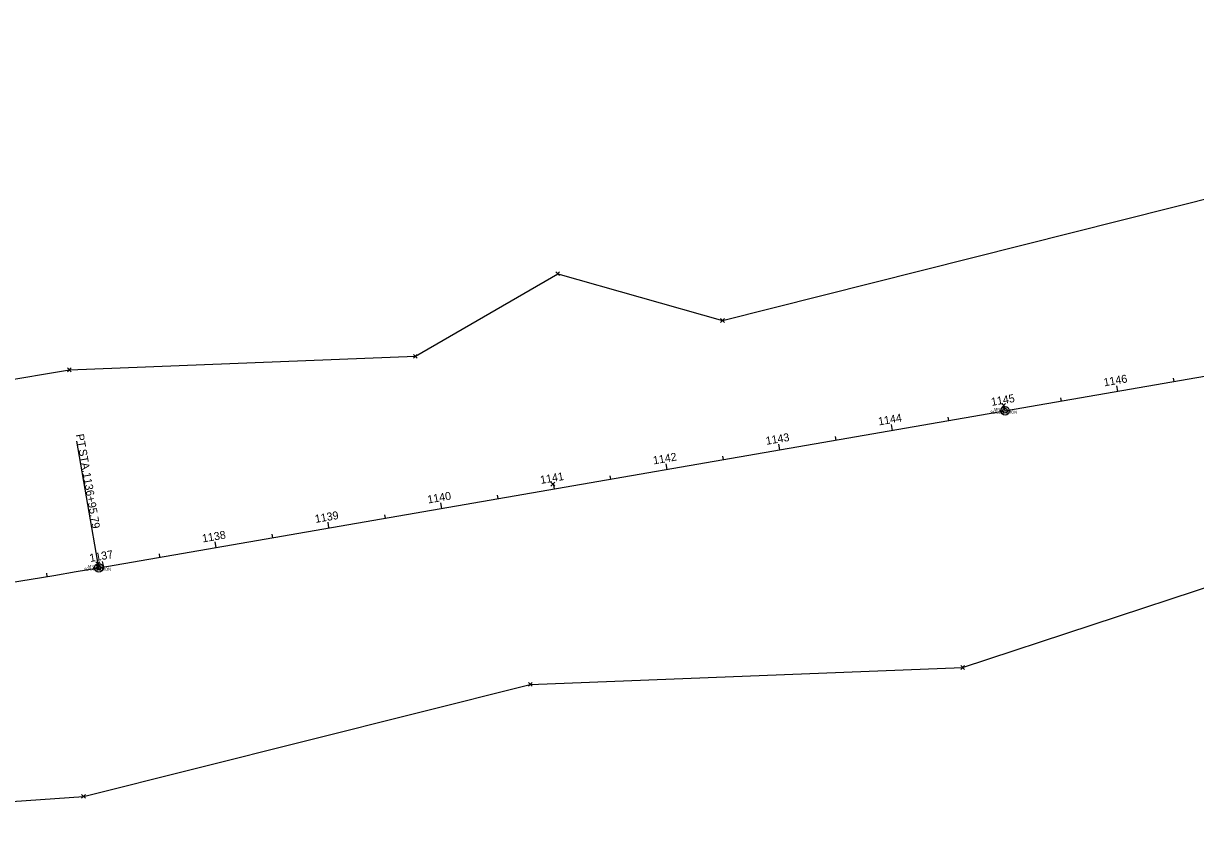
# Model space of a CAD drawing. Extents: x 2082101 to 2090447, y 708207 to 709766.
# Drawn here: x 2085236 to 2086260, y 708322 to 709029 of the extents above; entities that cross this region are included whole.
import ezdxf

# ---------------------------------------------------------------- set-up
doc = ezdxf.new("R2010")
doc.units = 0
for name, color, linetype in [('DR_X_Ditch', 7, 'Continuous'), ('DR_X_Elev_Flow', 7, 'Continuous'), ('GK_Drainage_Nodes', 7, 'Continuous'), ('SV_X_Break_Lines', 7, 'Continuous'), ('SV_X_Mon_Cells_Found', 7, 'Continuous'), ('SV_X_Shot_Marker', 7, 'Continuous'), ('SV_X_Text_Comment', 7, 'Continuous'), ('SV_X_Text_Elevation', 7, 'Continuous'), ('SV_X_Text_Name', 7, 'Continuous'), ('SV_X_Toe_of_Slope', 7, 'Continuous')]:
    doc.layers.add(name, color=color, linetype=linetype)

msp = doc.modelspace()

# ---------------------------------------------------------------- linework, layer by layer
at = {"layer": 'DR_X_Ditch'}
for p, q in [((2085846.9, 708768.7), (2086556.8, 708947.6)), ((2085578.3, 708737.4), (2085702.8, 708809.7)), ((2085578.3, 708737.4), (2085702.8, 708809.7)), ((2085702.8, 708809.7), (2085846.9, 708768.7)), ((2085702.8, 708809.7), (2085846.9, 708768.7)), ((2085275.9, 708725.5), (2085578.3, 708737.4)), ((2085275.9, 708725.5), (2085578.3, 708737.4)), ((2085180.1, 708709.7), (2085275.9, 708725.5)), ((2085180.1, 708709.7), (2085275.9, 708725.5)), ((2086056.8, 708465.1), (2086479.3, 708604.4)), ((2085678.8, 708450.3), (2086056.8, 708465.1)), ((2085288.2, 708352.3), (2085678.8, 708450.3)), ((2084856.3, 708322.4), (2085288.2, 708352.3))]:
    msp.add_line(p, q, dxfattribs=at)
at = {"layer": 'DR_X_Elev_Flow'}
msp.add_line((2085301.6, 708552.4), (2085282.4, 708663.2), dxfattribs=at)
msp.add_circle((2085301.6, 708552.4), 1.5, dxfattribs=at)
at = {"layer": 'GK_Drainage_Nodes'}
for p, q in [((2086192.5, 708706.8), (2086191.7, 708711.7)), ((2086241.8, 708715.3), (2086241.3, 708718.3)), ((2086143.3, 708698.3), (2086142.8, 708701.2)), ((2086094, 708689.7), (2086093.2, 708694.7)), ((2086044.7, 708681.2), (2086044.2, 708684.1)), ((2085995.5, 708672.6), (2085994.6, 708677.6)), ((2085897, 708655.6), (2085896.1, 708660.5)), ((2085946.2, 708664.1), (2085945.7, 708667.1)), ((2085847.7, 708647), (2085847.2, 708650)), ((2085798.4, 708638.5), (2085797.6, 708643.4)), ((2085749.2, 708630), (2085748.6, 708632.9)), ((2085699.9, 708621.4), (2085699, 708626.3)), ((2085601.4, 708604.3), (2085600.5, 708609.3)), ((2085650.6, 708612.9), (2085650.1, 708615.8)), ((2085552.1, 708595.8), (2085551.6, 708598.8)), ((2085502.8, 708587.3), (2085502, 708592.2)), ((2085453.6, 708578.7), (2085453.1, 708581.7)), ((2085404.3, 708570.2), (2085403.4, 708575.1)), ((2085305.8, 708553.1), (2085304.9, 708558)), ((2085355, 708561.6), (2085354.5, 708564.6)), ((2085256.5, 708544.7), (2085256, 708547.7))]:
    msp.add_line(p, q, dxfattribs=at)
at = {"layer": 'SV_X_Break_Lines'}
for p, q in [((2085701.1, 708808), (2085704.4, 708811.3)), ((2085701.1, 708811.3), (2085704.4, 708808)), ((2085845.2, 708767), (2085848.6, 708770.4)), ((2085845.2, 708770.4), (2085848.6, 708767)), ((2085576.6, 708735.7), (2085580, 708739)), ((2085576.6, 708739), (2085580, 708735.7)), ((2085274.2, 708723.9), (2085277.5, 708727.2)), ((2085274.2, 708727.2), (2085277.5, 708723.9)), ((2086055.2, 708463.5), (2086058.5, 708466.8)), ((2086055.2, 708466.8), (2086058.5, 708463.5)), ((2085677.1, 708448.7), (2085680.5, 708452)), ((2085677.1, 708452), (2085680.5, 708448.7)), ((2085286.5, 708350.7), (2085289.9, 708354)), ((2085286.5, 708354), (2085289.9, 708350.7))]:
    msp.add_line(p, q, dxfattribs=at)
at = {"layer": 'SV_X_Shot_Marker'}
msp.add_line((2085301.6, 708552.4), (2088049.6, 709028.7), dxfattribs=at)
msp.add_arc((2084323.5, 714201), 5732.7, 267.0489, 279.82352, dxfattribs=at)
at = {"layer": 'SV_X_Text_Name'}
for p, q in [((2086091, 708692.7), (2086094.3, 708696.1)), ((2086091, 708696.1), (2086094.3, 708692.7)), ((2085696.9, 708623.9), (2085700.3, 708627.2)), ((2085696.9, 708627.2), (2085700.3, 708623.9)), ((2085299, 708554.4), (2085302.3, 708557.7)), ((2085299, 708557.7), (2085302.3, 708554.4))]:
    msp.add_line(p, q, dxfattribs=at)
at = {"layer": 'SV_X_Toe_of_Slope'}
for centre, radius in [((2086093.9, 708689.8), 3.75), ((2086093.9, 708689.8), 2), ((2085301.6, 708552.4), 3.75), ((2085301.6, 708552.4), 2)]:
    msp.add_circle(centre, radius, dxfattribs=at)

# ---------------------------------------------------------------- texts
at = {"layer": 'DR_X_Elev_Flow'}
for s, p in [('PT', (2085281.5, 708668.9)), (' STA. ', (2085283.4, 708658.2)), ('1136+95.79', (2085287.4, 708635.2))]:
    msp.add_text(s, height=7, rotation=279.8336, dxfattribs=at).set_placement(p)
at = {"layer": 'GK_Drainage_Nodes'}
for s, p in [('1146', (2086180.7, 708711.1)), ('1145', (2086082.3, 708694)), ('1144', (2085983.6, 708676.9)), ('1143', (2085885.3, 708659.9)), ('1142', (2085786.7, 708642.8)), ('1141', (2085688.1, 708625.7)), ('1140', (2085589.5, 708608.6)), ('1139', (2085491.1, 708591.6)), ('1138', (2085392.5, 708574.5)), ('1137', (2085294, 708557.4))]:
    msp.add_text(s, height=7, rotation=9.8336, dxfattribs=at).set_placement(p)
at = {"layer": 'SV_X_Mon_Cells_Found'}
for p in [(2086093.9, 708687.3), (2085301.6, 708549.9)]:
    msp.add_text('CMON', height=2.5, dxfattribs=at).set_placement(p)
at = {"layer": 'SV_X_Text_Comment'}
for s, p in [('910.125', (2086081.2, 708687.3)), ('924.440', (2085288.8, 708549.9))]:
    msp.add_text(s, height=2.5, dxfattribs=at).set_placement(p)
at = {"layer": 'SV_X_Text_Elevation'}
for s, p in [('MN17', (2086084.3, 708689.8)), ('MN16', (2085292, 708552.4))]:
    msp.add_text(s, height=2.5, dxfattribs=at).set_placement(p)

doc.saveas('drawing.dxf')
